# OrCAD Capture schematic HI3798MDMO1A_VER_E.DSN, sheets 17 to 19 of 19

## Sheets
17 SHEET17: size Custom
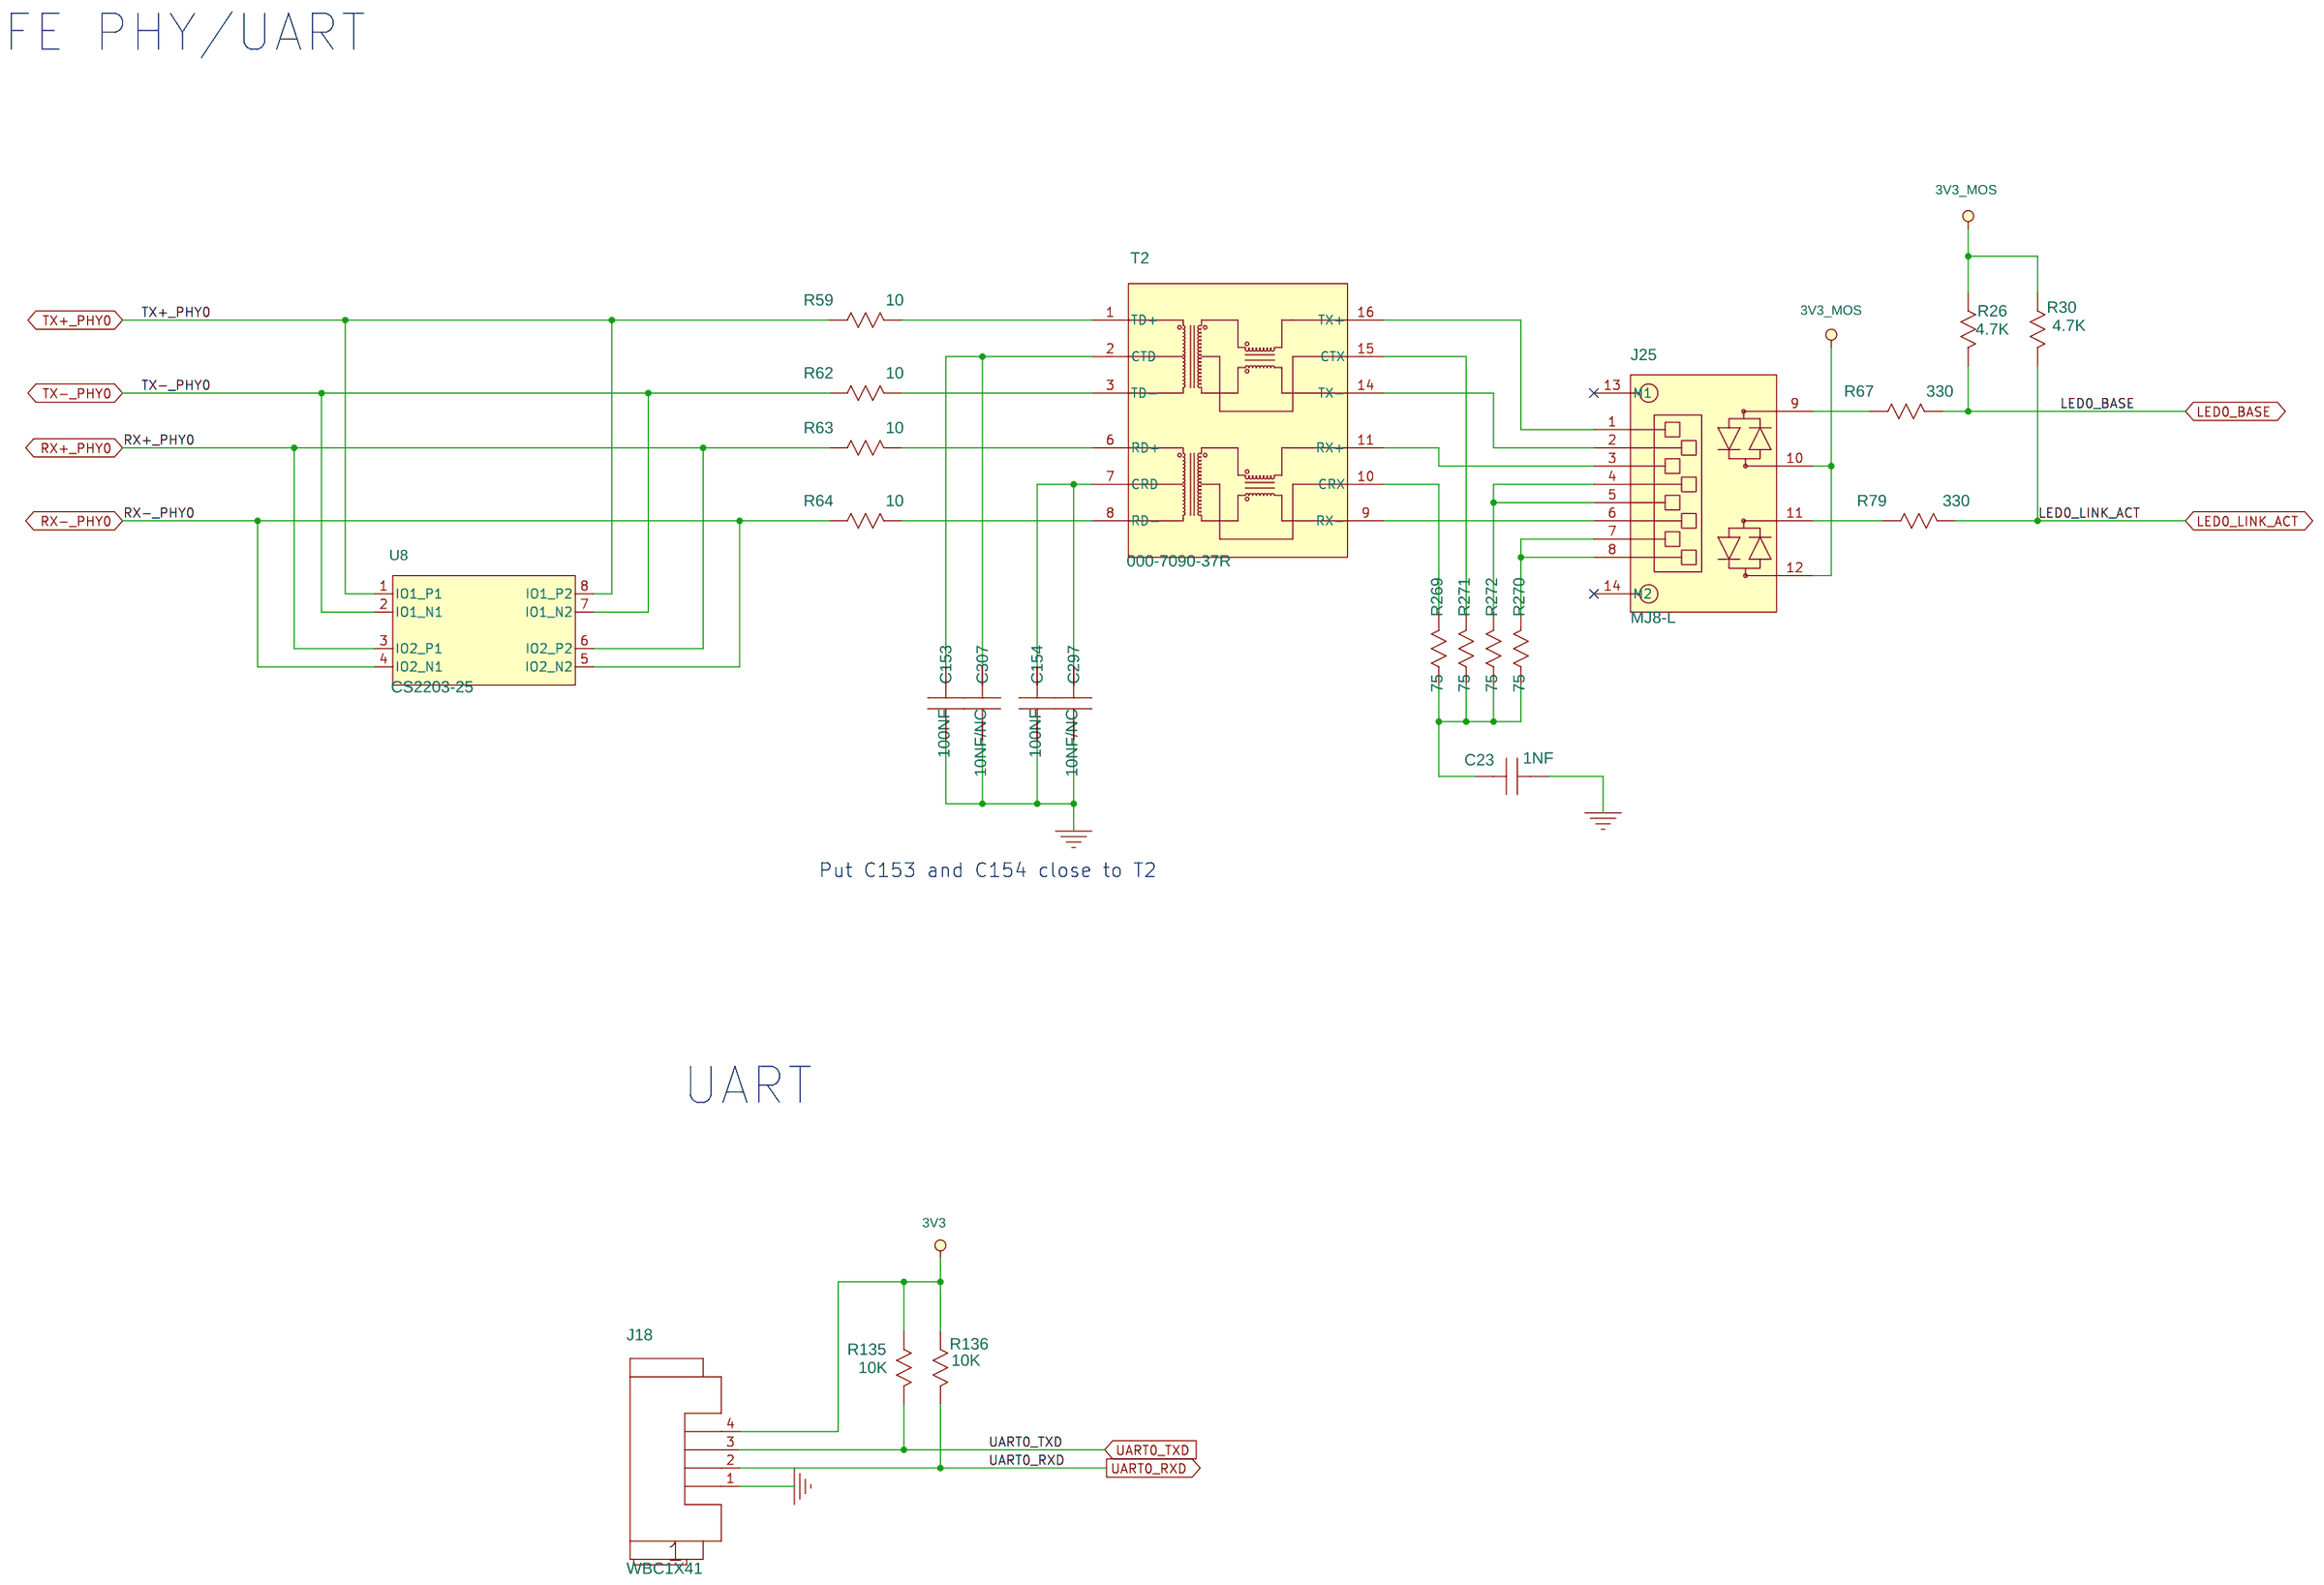
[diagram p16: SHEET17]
18 SHEET18: size A
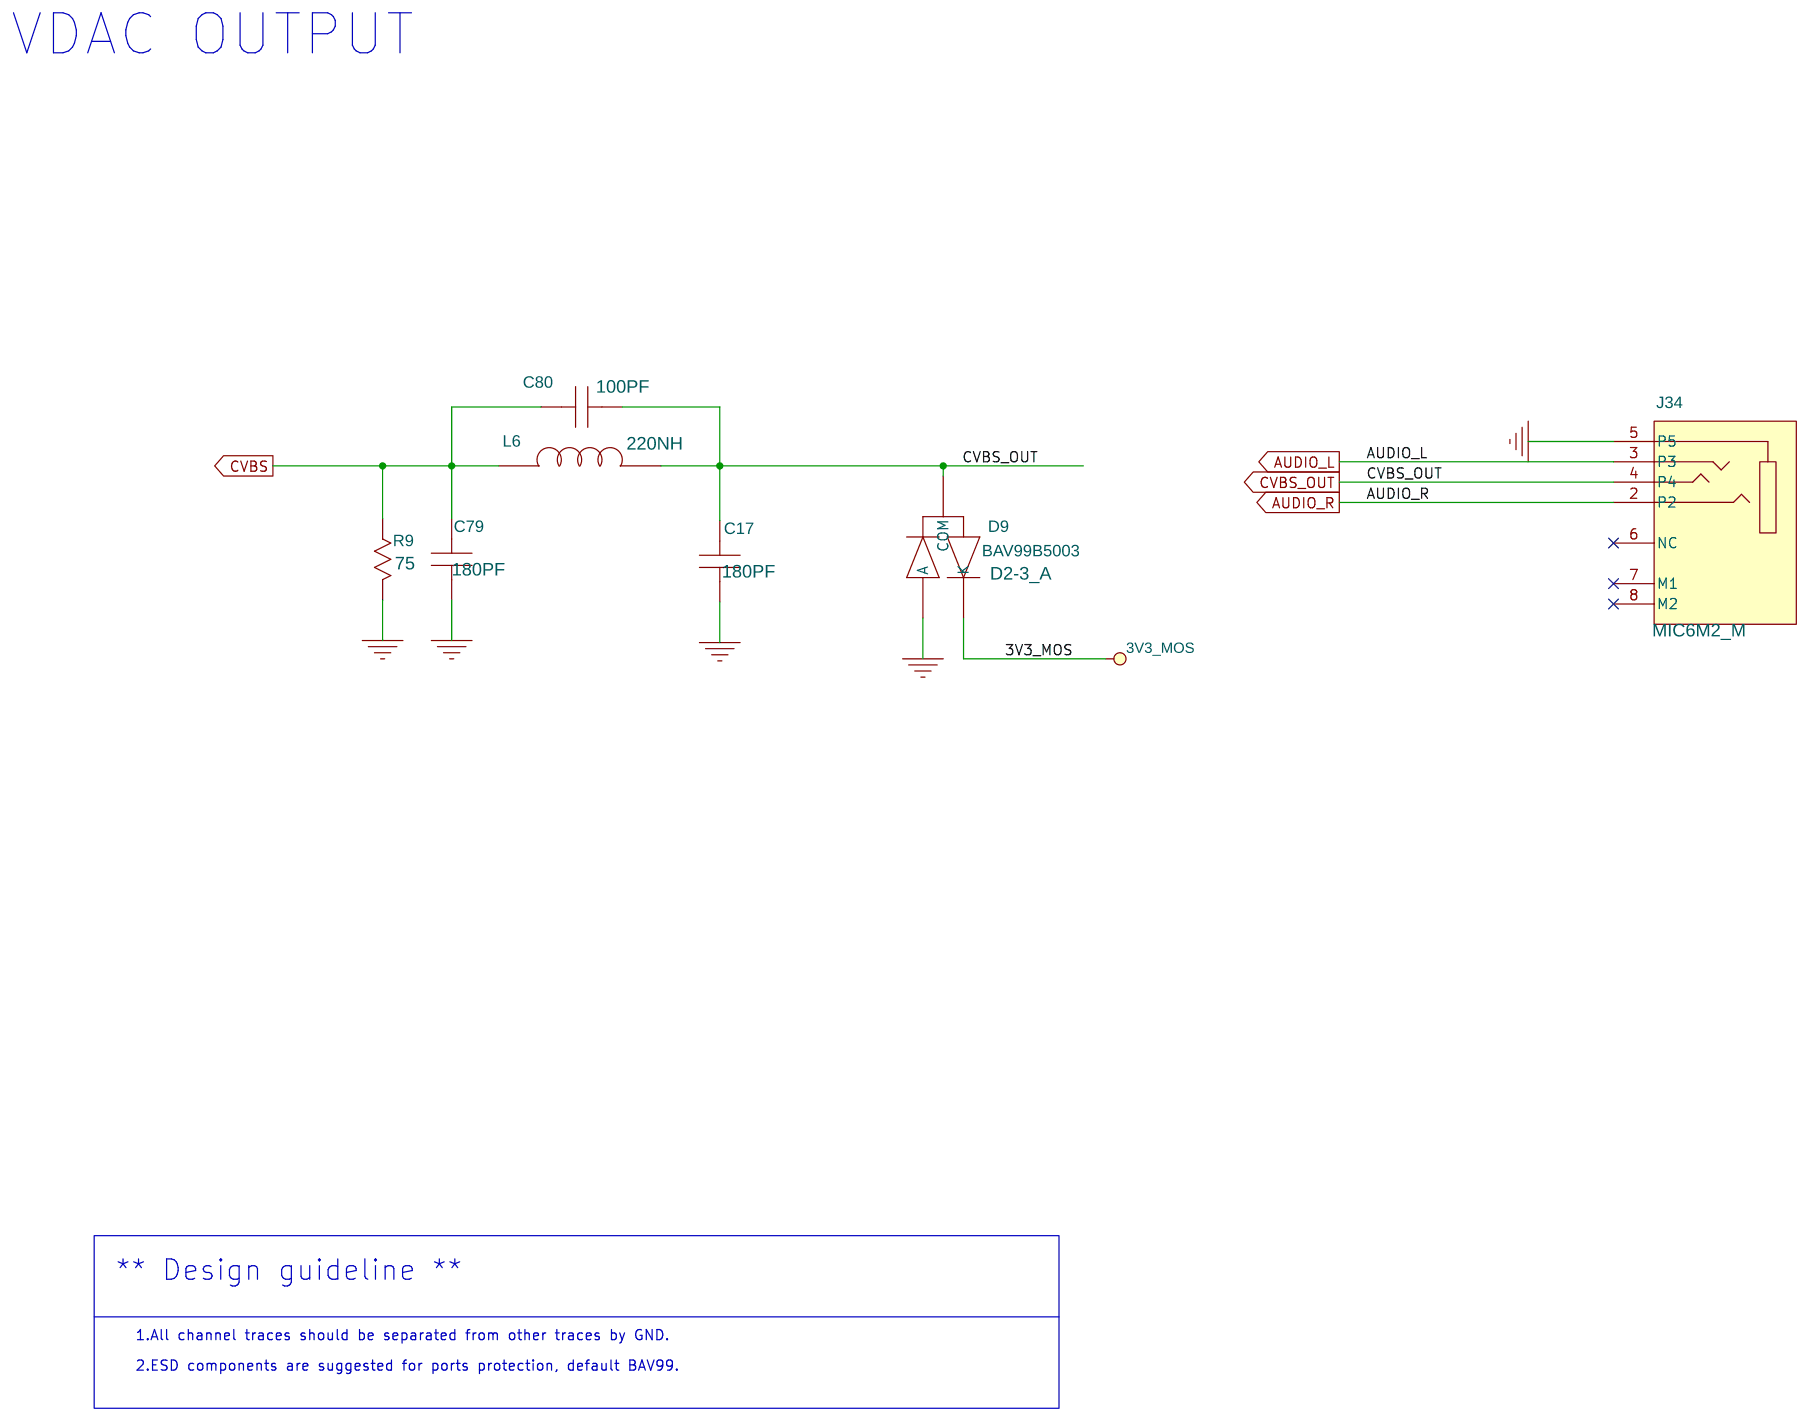
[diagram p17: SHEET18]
19 SHEET19: size Custom
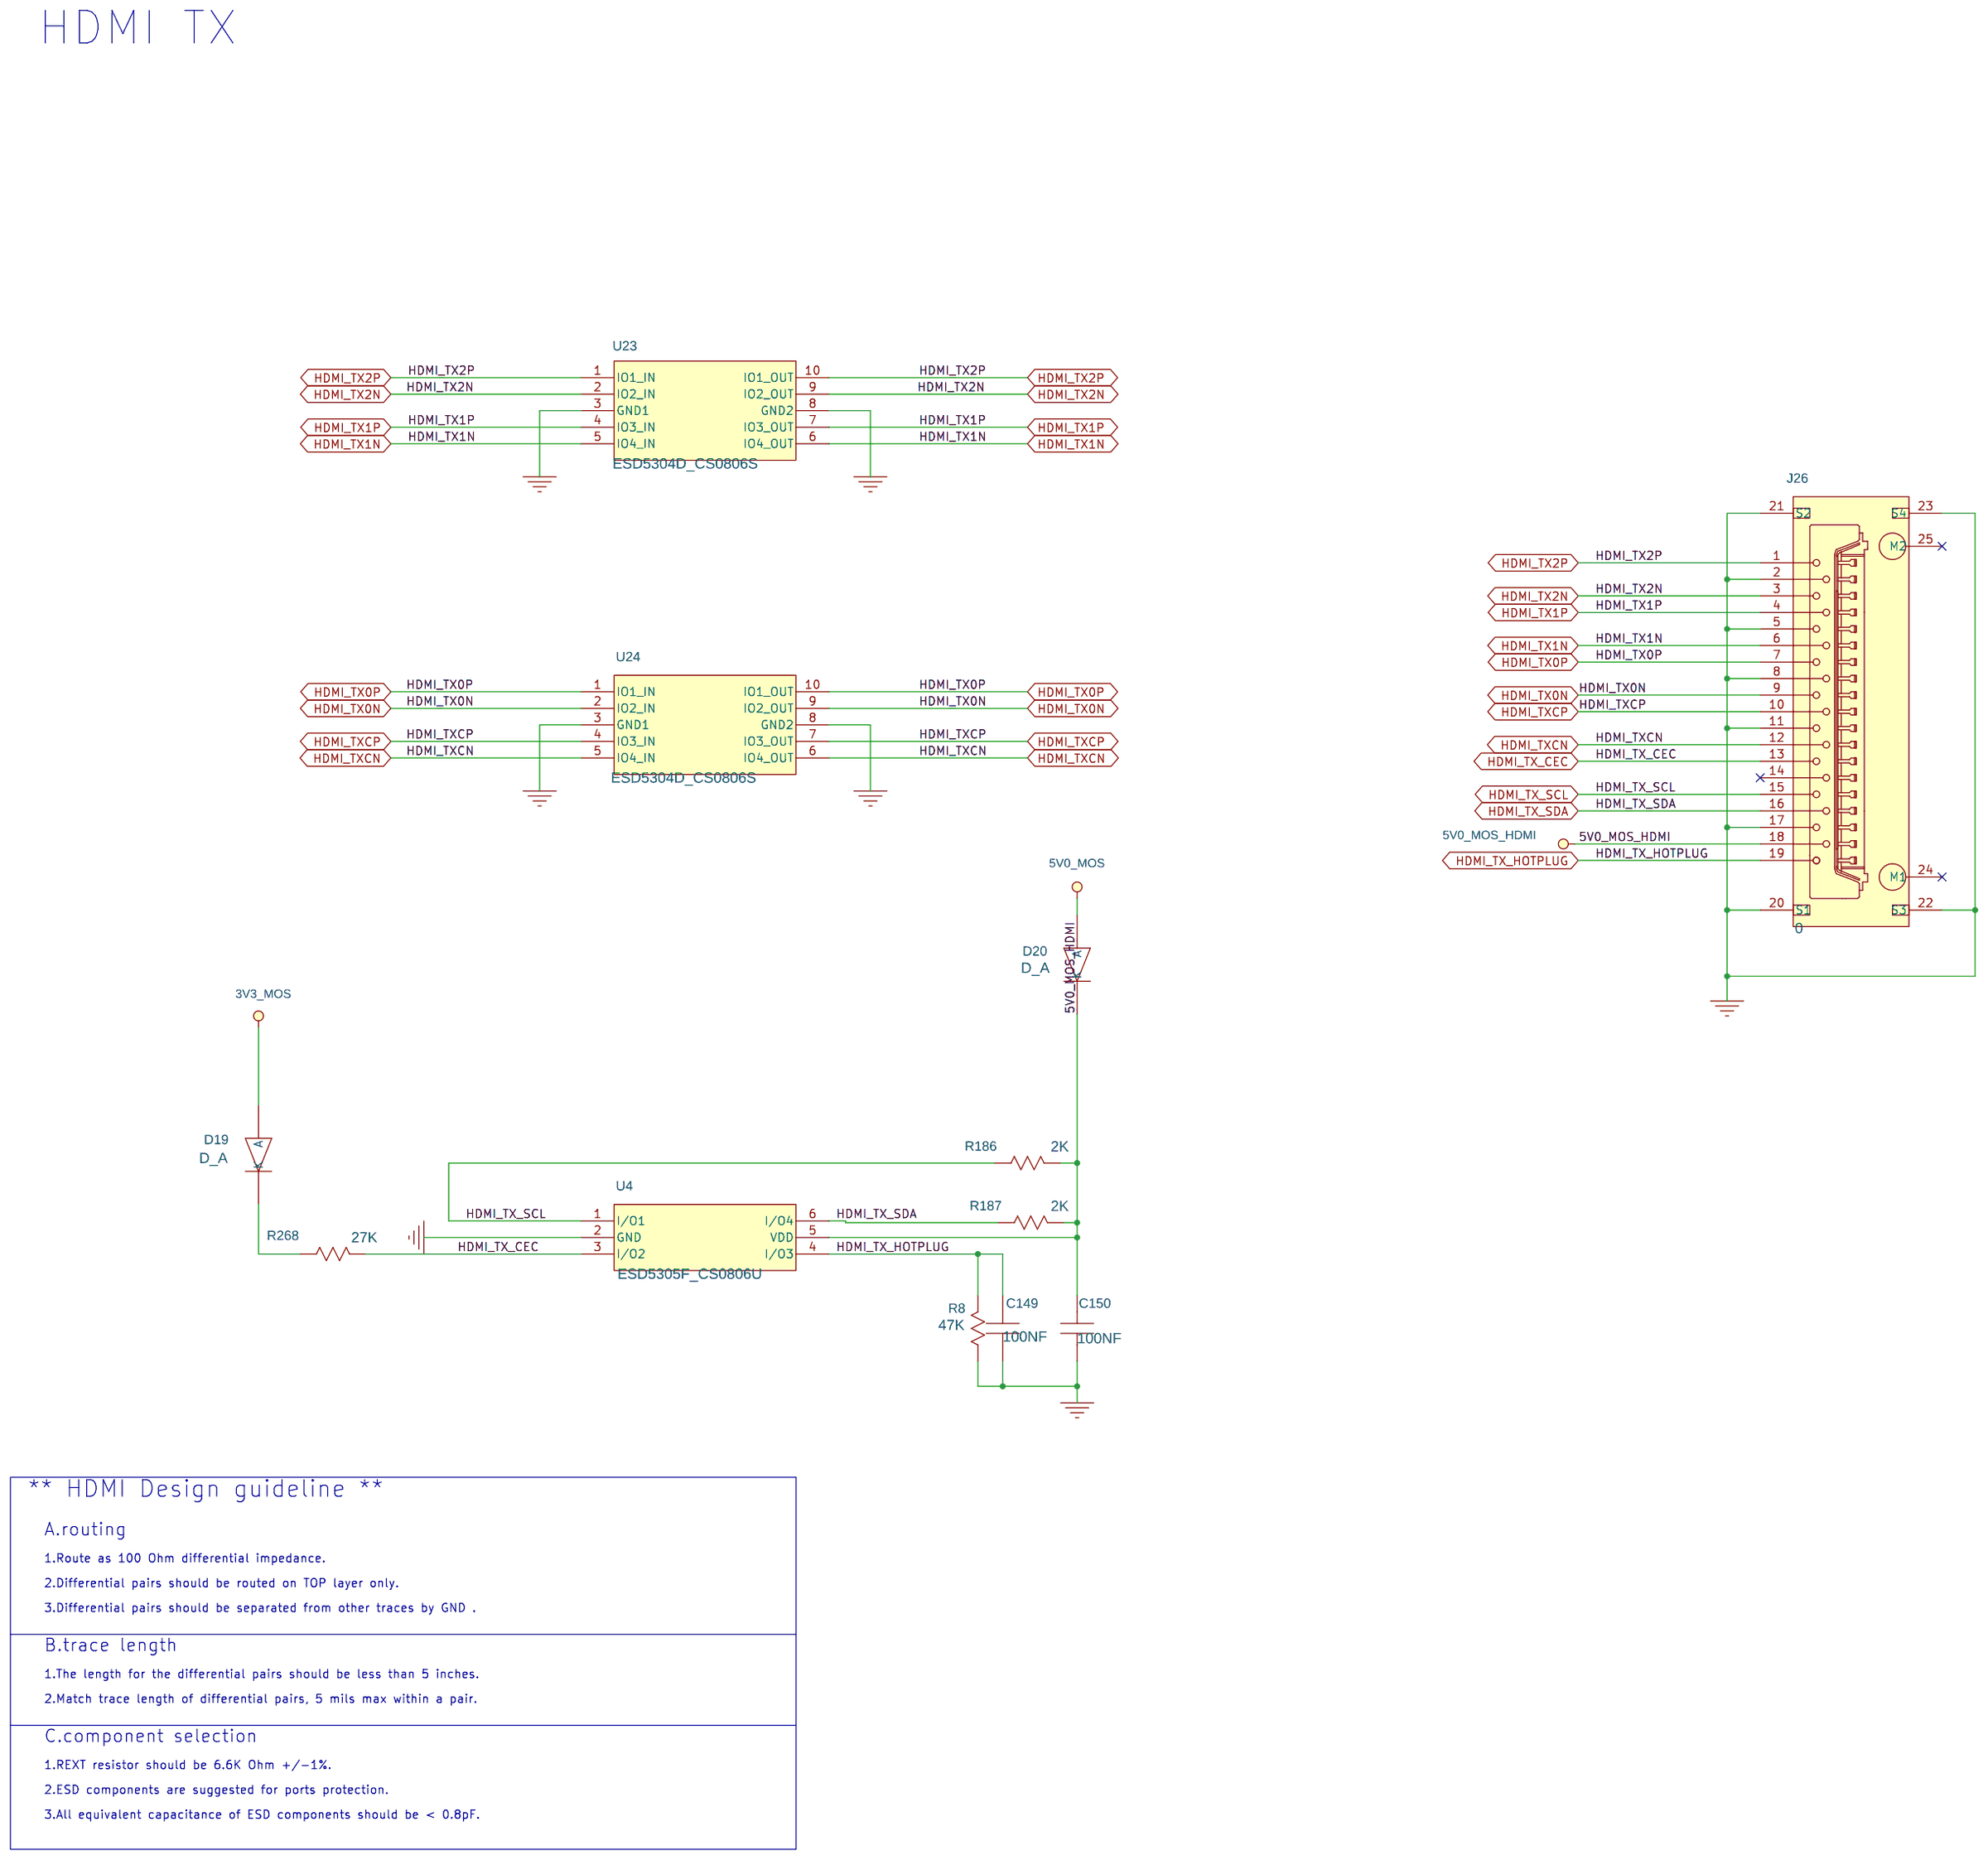
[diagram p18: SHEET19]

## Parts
sheet SHEET17
C23  1NF  [SC1206]
C153  100NF  [SC0402]
C154  100NF  [SC0402]
C297  10NF/NC  [SC0402]
C307  10NF/NC  [SC0402]
J18  WBC1X41  [WBC0104-49T]
J25  MJ8-L  [MJ8-RLY]
R26  4.7K  [SR0402]
R30  4.7K  [SR0402]
R59  10  [SR0402]
R62  10  [SR0402]
R63  10  [SR0402]
R64  10  [SR0402]
R67  330  [SR0402]
R79  330  [SR0402]
R135  10K  [SR0402]
R136  10K  [SR0402]
R269  75  [SR0805]
R270  75  [SR0805]
R271  75  [SR0805]
R272  75  [SR0805]
T2  000-7090-37R  [STFM16-50-285]
U8  CS2203-25  [RN8-0402]
sheet SHEET18
C17  180PF  [SC0402]
C79  180PF  [SC0402]
C80  100PF  [SC0402]
D9  D2-3_A  [SOT23]
J34  MIC6M2_M  [VAF6-1107]
L6  220NH  [SL0402]
R9  75  [SR0402]
sheet SHEET19
C149  100NF  [SC0402]
C150  100NF  [SC0402]
D19  D_A  [HSOD323A]
D20  D_A  [HSOD323A]
J26  0  [WBC0119-20R-A]
R8  47K  [SR0402]
R186  2K  [SR0402]
R187  2K  [SR0402]
R268  27K  [SR0402]
U4  ESD5305F_CS0806U  [SOT23A-6L]
U23  ESD5304D_CS0806S  [DFN2510P10E]
U24  ESD5304D_CS0806S  [DFN2510P10E]

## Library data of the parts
C23 = C: %182%%238%%182%%168%%185%%164%%215%%247%%181%%231%%209%%185%(V): 2000; %195%%232%%202%%246%: SMD陶瓷电容-2000V-1NF-+/-20%-X7R-1206; %208%%161%%192%%224%%195%%251%%179%%198%: SMD陶瓷电容; CODE: 8070439; COMPONENT_HIGH_MAX: 1.52MM; DEVICE: 1206GC102MAT1A
C153 C154 = C: %182%%238%%182%%168%%185%%164%%215%%247%%181%%231%%209%%185%(V): 16; %195%%232%%202%%246%: SMD陶瓷电容-16V-100NF-±10%-X7R-0402; %208%%161%%192%%224%%195%%251%%179%%198%: SMD陶瓷电容; CODE: 8070614; COMPONENT_HIGH_MAX: 0.6MM; DEVICE: RMEMK105BJ104KV_FR
C297 C307 = C: %182%%238%%182%%168%%185%%164%%215%%247%%181%%231%%209%%185%(V): 16; %195%%232%%202%%246%: SMD陶瓷电容-16V-10NF-+/-10%-X7R-0402-BT,TS16949; %208%%161%%192%%224%%195%%251%%179%%198%: SMD陶瓷电容; CODE: 8070449; COMPONENT_HIGH_MAX: 0.55MM; DEVICE: GRM155R71C103KA01D
J18 = WBC1X41: %195%%232%%202%%246%: 普通插座-4PIN-单排-直式-1.25MM-2MM-THT-1A; %208%%161%%192%%224%%195%%251%%179%%198%: 普通插座; CODE: 14100167; COMPONENT_HIGH_MAX: 4.2MM; DEVICE: SDW12501_4A_HW
J25 = MJ8-L: %195%%232%%202%%246%: 网口连接器-单排-单端口-8PIN-8BIT-非屏蔽-模型插座/侧面插入型-引脚长2.54MM-带固定脚/带灯; %208%%161%%192%%224%%195%%251%%179%%198%: 网口连接器; COMPONENT_HIGH_MAX: 13.2MM; DEVICE: 406533_1
R26 R30 = R: %182%%238%%182%%168%%185%%166%%194%%202%(W): 0.06; %195%%232%%202%%246%: 片式厚膜电阻器-0.0625W-4700OHM-+/-5%-0402; %208%%161%%192%%224%%195%%251%%179%%198%: 片式厚膜电阻器; %215%%232%%214%%181%%212%%202%%208%%237%%198%%171%%178%%238%: +/-5%; CODE: 7090793; COMPONENT_HIGH_MAX: 0.4MM; DEVICE: RK73B1ELTP472J
R59 R62-R64 R67 R79 = R: %182%%238%%182%%168%%185%%166%%194%%202%(W): 0.06; %195%%232%%202%%246%: 片式厚膜电阻器-0.0625W-330OHM-+/-1%-0402-BT; %208%%161%%192%%224%%195%%251%%179%%198%: 片式厚膜电阻器; %215%%232%%214%%181%%212%%202%%208%%237%%198%%171%%178%%238%: +/-1%; CODE: 7091333; COMPONENT_HIGH_MAX: 0.4MM; DEVICE: RC_02W3300FT
R135 R136 = R: %182%%238%%182%%168%%185%%166%%194%%202%(W): 0.06; %195%%232%%202%%246%: 片式厚膜电阻器-0.0625W-10000OHM-±5%-0402; %208%%161%%192%%224%%195%%251%%179%%198%: 片式厚膜电阻器; %215%%232%%214%%181%%212%%202%%208%%237%%198%%171%%178%%238%: ±5%; CODE: 7090815; COMPONENT_HIGH_MAX: 0.4MM; DEVICE: RC_02W103JT
R269-R272 = R: %182%%238%%182%%168%%185%%166%%194%%202%(W): 0.13; %195%%232%%202%%246%: 片式厚膜电阻器-0.125W-75OHM-±1%-0805; %208%%161%%192%%224%%195%%251%%179%%198%: 片式厚膜电阻器; %215%%232%%214%%181%%212%%202%%208%%237%%198%%171%%178%%238%: ±1%; CODE: 7090362; DEVICE: RC0805FR_0775R
T2 = 000-7090-37R: %195%%232%%202%%246%: LAN变压器-1CT:1CT-0.35MH-0UH-1路-2变压器-100BASE-T接口模块-SMT; %208%%161%%192%%224%%195%%251%%179%%198%: LAN变压器; CODE: 9050085; COMPONENT_HIGH_MAX: 6.2MM; DEVICE: H1102T
U8 = CS2203-25_1
C17 C79 = C: %182%%238%%182%%168%%185%%164%%215%%247%%181%%231%%209%%185%(V): 50; %195%%232%%202%%246%: SMD陶瓷电容-50V-0.18NF-+/-5%-NPO-0402; %208%%161%%192%%224%%195%%251%%179%%198%: SMD陶瓷电容; CODE: 8070637; COMPONENT_HIGH_MAX: 0.55MM; DEVICE: CC0402JRNPO9BB181
C80 = C: %182%%238%%182%%168%%185%%164%%215%%247%%181%%231%%209%%185%(V): 50; %195%%232%%202%%246%: SMD陶瓷电容-50V-0.1NF-±5%-NPO-0402; %208%%161%%192%%224%%195%%251%%179%%198%: SMD陶瓷电容; CODE: 8070450; COMPONENT_HIGH_MAX: 0.55MM; DEVICE: 04025A101JAT2A
D9 = D2-3_A: %195%%232%%202%%246%: 开关二极管-70V-200MA-1.25V-6NS-串联-SOT-23-2 FIT; %208%%161%%192%%224%%195%%251%%179%%198%: 开关二极管; CODE: 15010042; COMPONENT_HIGH_MAX: 1.26MM; DEVICE: BAV99B5003
J34 = MIC6M2_M: %195%%232%%202%%246%: 耳机连接器-3.5MM-5PIN-弯式-THT-00486672; CODE: 14240414; COMPONENT_HIGH_MAX: 5MM; DEVICE: 8967_3506ADT_M_A
L6 = L: %195%%232%%202%%246%: 贴片电感器-0.22UH-+/-5%-3.77OHM-0.3A-0402; %208%%161%%192%%224%%195%%251%%179%%198%: 贴片电感器; CODE: 10031264; COMPONENT_HIGH_MAX: 0.55MM; DEVICE: LGHK1005R22J_T
R9 = R: %182%%238%%182%%168%%185%%166%%194%%202%(W): 0.06; %195%%232%%202%%246%: 片式厚膜电阻器-0.0625W-75OHM-+/-1%-0402; %208%%161%%192%%224%%195%%251%%179%%198%: 片式厚膜电阻器; %215%%232%%214%%181%%212%%202%%208%%237%%198%%171%%178%%238%: +/-1%; CODE: 7091321; COMPONENT_HIGH_MAX: 0.4MM; DEVICE: RC_02W750FT
C149 C150 = C: %182%%238%%182%%168%%185%%164%%215%%247%%181%%231%%209%%185%(V): 16; %195%%232%%202%%246%: SMD陶瓷电容-16V-100NF-+/-10%-X7R-0402-BT; %208%%161%%192%%224%%195%%251%%179%%198%: SMD陶瓷电容; CODE: 8070614; COMPONENT_HIGH_MAX: 0.6MM; DEVICE: RMEMK105BJ104KV_FR
D19 D20 = D_A: %195%%232%%202%%246%: 肖特基二极管-10V-3A-0.24V-SOD323-BT; %208%%161%%192%%224%%195%%251%%179%%198%: 肖特基二极管; CODE: 15010252; COMPONENT_HIGH_MAX: 1.1MM; DEVICE: BAT60BE6327
J26 = WBC1X19S4M2: %195%%232%%202%%246%: IO连接器-HDMI 母座-19PIN-弯式-SMT带DIP脚-终端专用; %208%%161%%192%%224%%195%%251%%179%%198%: IO连接器; CODE: 14240146; COMPONENT_HIGH_MAX: 6.38MM; DEVICE: 1827059_3
R8 = R: %182%%238%%182%%168%%185%%166%%194%%202%(W): 0.06; %195%%232%%202%%246%: 片式厚膜电阻器-0.0625W-47000OHM-+/-5%-0402-ELOM; %208%%161%%192%%224%%195%%251%%179%%198%: 片式厚膜电阻器; %215%%232%%214%%181%%212%%202%%208%%237%%198%%171%%178%%238%: +/-5%; CODE: 7090819; DEVICE: RC0402JR_0747K
R186 R187 = R: %182%%238%%182%%168%%185%%166%%194%%202%(W): 0.06; %195%%232%%202%%246%: 片式厚膜电阻器-0.0625W-2000OHM-+/-1%-0402-BT; %208%%161%%192%%224%%195%%251%%179%%198%: 片式厚膜电阻器; %215%%232%%214%%181%%212%%202%%208%%237%%198%%171%%178%%238%: +/-1%; CODE: 7091354; COMPONENT_HIGH_MAX: 0.4MM; DEVICE: RC_02W2001FT
R268 = R: %182%%238%%182%%168%%185%%166%%194%%202%(W): 0.06; %195%%232%%202%%246%: 片式厚膜电阻器-0.0625W-27000OHM-+/-5%-0402; %208%%161%%192%%224%%195%%251%%179%%198%: 片式厚膜电阻器; %215%%232%%214%%181%%212%%202%%208%%237%%198%%171%%178%%238%: +/-5%; CODE: 7090852; COMPONENT_HIGH_MAX: 0.4MM; DEVICE: RK73B1ETTP273J
U4 = CS0806U
U23 = CS0806S: #: 3
U24 = CS0806S

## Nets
3V3: J18.4 R135.1(A) R136.1(A) ; also on sheet 6 7 8 11 15
3V3_MOS: D9.2(K) D19.2(A) J25.10 J25.12 R26.1(A) R30.1(A) ; also on sheet 7 8 9 10 11 13 14 15
5V0_MOS: D20.2(A) ; also on sheet 7 14 16
5V0_MOS_HDMI: C150.1(A) D20.1(K) J26.18 R186.2(B) R187.2(B) U4.5(VDD)
GND: C17.2(B) C23.2(B) C79.2(B) C149.2(B) C150.2(B) C153.2(B) C154.2(B) C297.2(B) C307.2(B) D9.1(A) J18.1 J26.2 J26.5 J26.8 J26.11 J26.17 J26.20(S1) J26.21(S2) J26.22(S3) J26.23(S4) J34.5(P5) R8.1(A) R9.2(B) U4.2(GND) U23.3(GND1) U23.8(GND2) U24.3(GND1) U24.8(GND2) ; also on sheet 1 2 5 6 7 8 9 10 11 12 13 14 15 16
AUDIO_L: J34.3(P3) ; also on sheet 16
AUDIO_R: J34.2(P2) ; also on sheet 16
CVBS: C79.1(A) C80.1(A) L6.1(A) R9.1(A) ; also on sheet 9
CVBS_OUT: C17.1(A) C80.2(B) D9.3(COM) J34.4(P4) L6.2(B)
HDMI_TX0N: J26.9 U24.2(IO2_IN) U24.9(IO2_OUT) ; also on sheet 9
HDMI_TX0P: J26.7 U24.1(IO1_IN) U24.10(IO1_OUT) ; also on sheet 9
HDMI_TX1N: J26.6 U23.5(IO4_IN) U23.6(IO4_OUT) ; also on sheet 9
HDMI_TX1P: J26.4 U23.4(IO3_IN) U23.7(IO3_OUT) ; also on sheet 9
HDMI_TX2N: J26.3 U23.2(IO2_IN) U23.9(IO2_OUT) ; also on sheet 9
HDMI_TX2P: J26.1 U23.1(IO1_IN) U23.10(IO1_OUT) ; also on sheet 9
HDMI_TX_CEC: J26.13 R268.2(B) U4.3(I/O2) ; also on sheet 9
HDMI_TX_HOTPLUG: C149.1(A) J26.19 R8.2(B) U4.4(I/O3) ; also on sheet 9
HDMI_TX_SCL: J26.15 R186.1(A) U4.1(I/O1) ; also on sheet 9
HDMI_TX_SDA: J26.16 R187.1(A) U4.6(I/O4) ; also on sheet 9
HDMI_TXCN: J26.12 U24.5(IO4_IN) U24.6(IO4_OUT) ; also on sheet 9
HDMI_TXCP: J26.10 U24.4(IO3_IN) U24.7(IO3_OUT) ; also on sheet 9
LED0_BASE: R26.2(B) R67.2(B) ; also on sheet 8
LED0_LINK_ACT: R30.2(B) R79.2(B) ; also on sheet 8
RX+_PHY0: R63.1(A) U8.3(IO2_P1) U8.6(IO2_P2) ; also on sheet 8
RX-_PHY0: R64.1(A) U8.4(IO2_N1) U8.5(IO2_N2) ; also on sheet 8
TX+_PHY0: R59.1(A) U8.1(IO1_P1) U8.8(IO1_P2) ; also on sheet 8
TX-_PHY0: R62.1(A) U8.2(IO1_N1) U8.7(IO1_N2) ; also on sheet 8
UART0_RXD: J18.2 R136.2(B) ; also on sheet 9
UART0_TXD: J18.3 R135.2(B) ; also on sheet 9
N00501: D19.1(K) R268.1(A)
N01120: R64.2(B) T2.8(RD-)
N01124: R63.2(B) T2.6(RD+)
N01128: R62.2(B) T2.3(TD-)
N01132: R59.2(B) T2.1(TD+)
N01184: C153.1(A) C307.1(A) T2.2(CTD)
N01194: J25.4 J25.5 R272.2(B)
N01204: J25.2 T2.14(TX-)
N01212: J25.1 T2.16(TX+)
N01220: C23.1(A) R269.1(A) R270.1(A) R271.1(A) R272.1(A)
N01240: J25.3 T2.11(RX+)
N01248: J25.6 T2.9(RX-)
N01252: R269.2(B) T2.10(CRX)
N01258: R271.2(B) T2.15(CTX)
N01264: J25.7 J25.8 R270.2(B)
N01274: J25.11 R79.1(A)
N01278: J25.9 R67.1(A)
N01282: C154.1(A) C297.1(A) T2.7(CRD)

Not connected (* = marked no-connect by the designer): J25 13(M1)* 14(M2)*; J26 14* 24(M1)* 25(M2)*; J34 6(NC)* 7(M1)* 8(M2)*

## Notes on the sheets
sheet 17
- FE PHY/UART
- Put C153 and C154 close to T2
- UART
sheet 18
- VDAC OUTPUT
- ** Design guideline **
- 1.All channel traces should be separated from other traces by GND.
- 2.ESD components are suggested for ports protection, default BAV99.
sheet 19
- HDMI TX
- ** HDMI Design guideline **
- A.routing
- 1.Route as 100 Ohm differential impedance.
- 2.Differential pairs should be routed on TOP layer only.
- 3.Differential pairs should be separated from other traces by GND .
- B.trace length
- 1.The length for the differential pairs should be less than 5 inches.
- 2.Match trace length of differential pairs, 5 mils max within a pair.
- C.component selection
- 1.REXT resistor should be 6.6K Ohm +/-1%.
- 2.ESD components are suggested for ports protection.
- 3.All equivalent capacitance of ESD components should be < 0.8pF.
